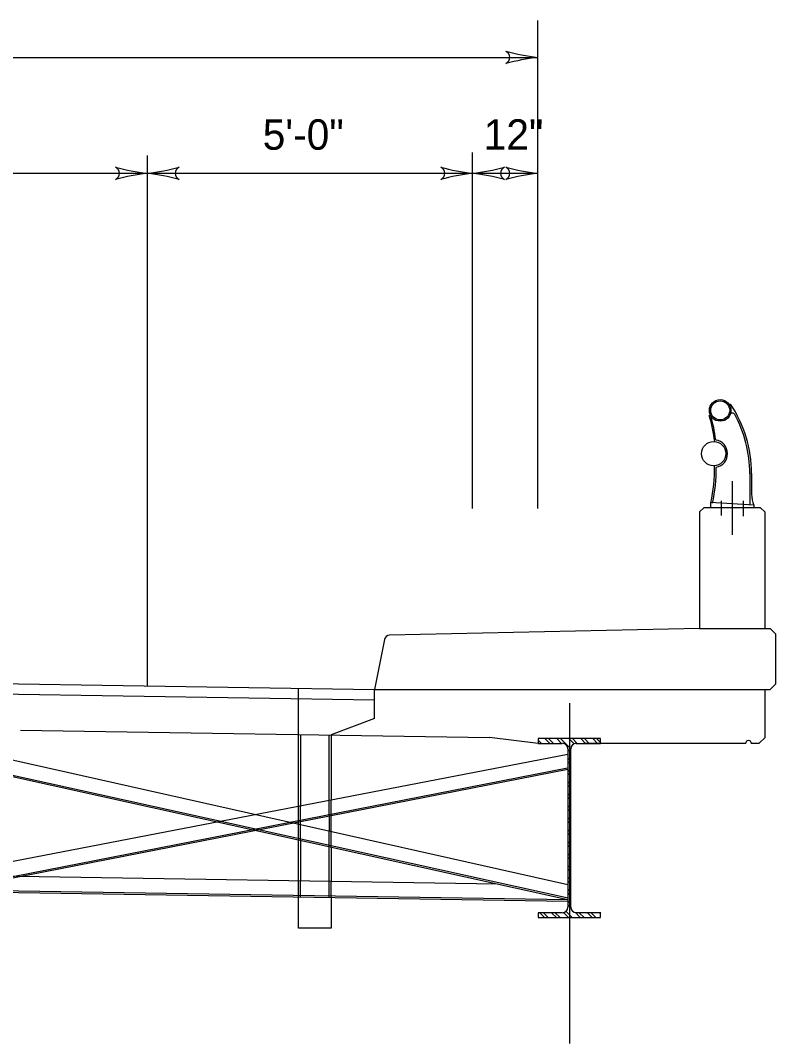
# Model space of a CAD drawing. Extents: x 10803 to 14007, y 6159 to 7440.
# Drawn here: x 13672.33 to 13683.94, y 6286.82 to 6302.55 of the extents above; entities that cross this region are included whole.
import ezdxf

# ---------------------------------------------------------------- set-up
doc = ezdxf.new("R2010")
doc.units = 0
for name, color, linetype in [('BR_X_Rail_Object', 7, 'Continuous'), ('BR_X_Slab_Const_Joint', 7, 'Continuous'), ('BR_X_Slab_Object', 7, 'Continuous'), ('Default', 7, 'Continuous')]:
    doc.layers.add(name, color=color, linetype=linetype)

msp = doc.modelspace()

# ---------------------------------------------------------------- linework, layer by layer
at = {"layer": 'BR_X_Rail_Object'}
for p, q in [((13683.231, 6296.638), (13683.249, 6296.648)), ((13682.922, 6296.472), (13682.941, 6296.478)), ((13683.547, 6295.584), (13683.547, 6295.098)), ((13683.573, 6295.582), (13683.573, 6295.265)), ((13682.943, 6295.133), (13682.943, 6295.051)), ((13683.606, 6295.094), (13682.943, 6295.133)), ((13683.606, 6295.094), (13683.606, 6295.051))]:
    msp.add_line(p, q, dxfattribs=at)
for centre, radius in [((13683.09, 6296.551), 0.166), ((13683.09, 6296.551), 0.146), ((13682.989, 6295.885), 0.187)]:
    msp.add_circle(centre, radius, dxfattribs=at)
for centre, radius, start, end in [((13681.655, 6295.584), 1.916, 359.9287, 33.7121), ((13680.872, 6295.841), 2.146, 6.1531, 17.1122), ((13680.872, 6295.841), 2.165, 6.8219, 17.1122), ((13683.279, 6296.471), 0.0394, 28.6512, 157.265), ((13681.655, 6295.584), 1.89, 359.9287, 28.6512), ((13682.989, 6295.885), 0.213, 280.8945, 81.1945), ((13680.838, 6295.635), 2.165, 346.5742, 1.6594), ((13680.838, 6295.635), 2.192, 346.5742, 1.0208), ((13684.072, 6295.271), 0.499, 180.6213, 200.7537)]:
    msp.add_arc(centre, radius, start, end, dxfattribs=at)
at = {"layer": 'BR_X_Slab_Const_Joint'}
for p, q in [((13682.774, 6293.198), (13683.774, 6293.198)), ((13677.774, 6292.26), (13683.774, 6292.26))]:
    msp.add_line(p, q, dxfattribs=at)
at = {"layer": 'BR_X_Slab_Object'}
for p, q in [((13682.774, 6294.989), (13682.837, 6295.051)), ((13682.774, 6294.989), (13682.774, 6293.198)), ((13683.712, 6295.051), (13682.837, 6295.051)), ((13683.774, 6294.989), (13683.712, 6295.051)), ((13683.774, 6294.989), (13683.774, 6293.198)), ((13682.774, 6293.198), (13678.008, 6293.095)), ((13683.774, 6293.198), (13683.858, 6293.198)), ((13683.858, 6293.198), (13683.941, 6293.114)), ((13683.941, 6293.114), (13683.941, 6292.344)), ((13677.928, 6293.028), (13677.774, 6292.26)), ((13651.774, 6292.666), (13677.774, 6292.26)), ((13651.774, 6292.508), (13677.774, 6292.101)), ((13683.941, 6292.344), (13683.858, 6292.26)), ((13677.774, 6292.101), (13677.774, 6292.26)), ((13683.774, 6292.26), (13683.858, 6292.26)), ((13683.774, 6292.26), (13683.774, 6291.519)), ((13672.334, 6291.637), (13679.542, 6291.524)), ((13680.292, 6291.432), (13679.542, 6291.524)), ((13683.691, 6291.436), (13683.774, 6291.519)), ((13680.993, 6291.436), (13683.483, 6291.436)), ((13683.564, 6291.436), (13683.691, 6291.436))]:
    msp.add_line(p, q, dxfattribs=at)
for centre, radius, start, end in [((13678.01, 6293.012), 0.0833, 91.2327, 168.6901), ((13683.524, 6291.436), 0.0417, 0, 180.0018)]:
    msp.add_arc(centre, radius, start, end, dxfattribs=at)
at = {"layer": 'Default'}
for p, q in [((13680.285, 6295.044), (13680.285, 6302.547)), ((13679.796, 6302.072), (13679.796, 6302.072)), ((13623.264, 6301.979), (13680.285, 6301.979)), ((13679.285, 6295.044), (13679.285, 6300.514)), ((13674.285, 6292.315), (13674.285, 6300.469)), ((13674.285, 6300.196), (13651.774, 6300.196)), ((13679.285, 6300.196), (13674.285, 6300.196)), ((13674.773, 6300.289), (13674.774, 6300.289)), ((13680.285, 6300.196), (13679.285, 6300.196)), ((13679.773, 6300.289), (13679.774, 6300.289)), ((13673.796, 6300.103), (13673.796, 6300.103)), ((13678.796, 6300.103), (13678.796, 6300.103)), ((13679.796, 6300.103), (13679.796, 6300.103)), ((13683.274, 6295.463), (13683.274, 6294.64)), ((13683.107, 6295.16), (13683.107, 6294.933)), ((13683.442, 6295.16), (13683.442, 6294.927)), ((13676.608, 6290.467), (13676.608, 6292.279)), ((13677.774, 6291.814), (13677.774, 6292.101)), ((13680.774, 6292.05), (13680.774, 6286.816)), ((13677.774, 6291.814), (13677.108, 6291.562)), ((13676.639, 6291.57), (13676.639, 6290.473)), ((13677.077, 6290.558), (13677.077, 6291.563)), ((13677.108, 6291.562), (13677.108, 6290.564)), ((13671.128, 6291.42), (13680.747, 6289.261)), ((13681.25, 6291.505), (13680.292, 6291.505)), ((13680.292, 6291.505), (13680.292, 6291.432)), ((13680.342, 6291.432), (13680.292, 6291.482)), ((13680.292, 6291.432), (13680.663, 6291.432)), ((13680.469, 6291.432), (13680.396, 6291.505)), ((13680.526, 6291.432), (13680.453, 6291.505)), ((13680.653, 6291.432), (13680.58, 6291.505)), ((13680.795, 6291.347), (13680.637, 6291.505)), ((13680.846, 6291.423), (13680.764, 6291.505)), ((13680.893, 6291.432), (13680.821, 6291.505)), ((13680.878, 6291.432), (13681.25, 6291.432)), ((13680.878, 6291.432), (13680.878, 6291.432)), ((13681.021, 6291.432), (13680.948, 6291.505)), ((13681.077, 6291.432), (13681.004, 6291.505)), ((13681.205, 6291.432), (13681.132, 6291.505)), ((13681.25, 6291.443), (13681.188, 6291.505)), ((13681.25, 6291.432), (13681.25, 6291.505)), ((13671.128, 6289.411), (13680.747, 6291.265)), ((13680.747, 6291.349), (13680.747, 6288.911)), ((13680.795, 6291.29), (13680.747, 6291.338)), ((13680.795, 6291.163), (13680.747, 6291.211)), ((13680.795, 6288.911), (13680.795, 6291.349)), ((13680.747, 6289.028), (13671.128, 6291.156)), ((13671.128, 6289.174), (13680.743, 6291.057)), ((13680.751, 6289.049), (13671.133, 6291.177)), ((13680.795, 6291.106), (13680.747, 6291.155)), ((13671.128, 6289.153), (13680.747, 6291.037)), ((13680.795, 6290.979), (13680.747, 6291.027)), ((13680.795, 6290.922), (13680.747, 6290.971)), ((13680.795, 6290.795), (13680.747, 6290.843)), ((13680.795, 6290.738), (13680.747, 6290.787)), ((13680.795, 6290.611), (13680.747, 6290.66)), ((13680.795, 6290.555), (13680.747, 6290.603)), ((13676.608, 6289.944), (13676.608, 6290.467)), ((13676.639, 6289.937), (13676.639, 6290.473)), ((13677.077, 6290.318), (13677.077, 6290.558)), ((13677.108, 6290.324), (13677.108, 6290.564)), ((13680.795, 6290.427), (13680.747, 6290.476)), ((13680.795, 6290.371), (13680.747, 6290.419)), ((13677.077, 6290.318), (13677.077, 6290.085)), ((13677.108, 6290.078), (13677.108, 6290.324)), ((13680.795, 6290.244), (13680.747, 6290.292)), ((13680.795, 6290.187), (13680.747, 6290.235)), ((13680.795, 6290.06), (13680.747, 6290.108)), ((13676.608, 6289.316), (13676.608, 6289.944)), ((13677.077, 6289.84), (13677.077, 6290.085)), ((13677.108, 6289.833), (13677.108, 6290.078)), ((13680.795, 6290.003), (13680.747, 6290.051)), ((13676.639, 6289.937), (13676.639, 6289.316)), ((13677.077, 6289.309), (13677.077, 6289.84)), ((13677.108, 6289.833), (13677.108, 6289.309)), ((13680.795, 6289.876), (13680.747, 6289.924)), ((13680.795, 6289.819), (13680.747, 6289.868)), ((13680.795, 6289.692), (13680.747, 6289.74)), ((13680.795, 6289.635), (13680.747, 6289.684)), ((13680.795, 6289.508), (13680.747, 6289.556)), ((13680.795, 6289.452), (13680.747, 6289.5)), ((13679.661, 6289.268), (13671.128, 6289.403)), ((13676.608, 6289.066), (13676.608, 6289.316)), ((13676.639, 6289.066), (13676.639, 6289.316)), ((13680.795, 6289.324), (13680.747, 6289.373)), ((13680.795, 6289.268), (13680.747, 6289.316)), ((13680.747, 6289.027), (13671.128, 6289.179)), ((13680.743, 6289.001), (13671.128, 6289.153)), ((13677.077, 6289.059), (13677.077, 6289.309)), ((13677.108, 6289.059), (13677.108, 6289.309)), ((13680.795, 6289.14), (13680.747, 6289.189)), ((13676.608, 6288.592), (13676.608, 6289.066)), ((13677.108, 6289.059), (13677.108, 6288.592)), ((13680.795, 6289.084), (13680.747, 6289.132)), ((13680.795, 6288.957), (13680.747, 6289.005)), ((13680.813, 6288.755), (13680.718, 6288.85)), ((13680.797, 6288.898), (13680.747, 6288.948)), ((13680.663, 6288.828), (13680.292, 6288.828)), ((13680.292, 6288.828), (13680.292, 6288.755)), ((13680.292, 6288.755), (13681.25, 6288.755)), ((13680.389, 6288.755), (13680.316, 6288.828)), ((13680.445, 6288.755), (13680.372, 6288.828)), ((13680.572, 6288.755), (13680.499, 6288.828)), ((13680.629, 6288.755), (13680.556, 6288.828)), ((13680.756, 6288.755), (13680.68, 6288.831)), ((13680.94, 6288.755), (13680.864, 6288.832)), ((13681.25, 6288.828), (13680.878, 6288.828)), ((13680.997, 6288.755), (13680.924, 6288.828)), ((13681.124, 6288.755), (13681.051, 6288.828)), ((13681.181, 6288.755), (13681.108, 6288.828)), ((13681.25, 6288.813), (13681.235, 6288.828)), ((13681.25, 6288.755), (13681.25, 6288.835)), ((13677.108, 6288.592), (13676.608, 6288.592))]:
    msp.add_line(p, q, dxfattribs=at)
for centre, radius, start, end in [((13680.724, 6305.633), 3.68, 255.3829, 263.1374), ((13680.724, 6298.325), 3.68, 96.8626, 104.6171), ((13674.724, 6303.85), 3.68, 255.3829, 263.1374), ((13674.724, 6296.542), 3.68, 96.8626, 104.6171), ((13673.845, 6303.85), 3.68, 276.8626, 284.6171), ((13673.845, 6296.542), 3.68, 75.3829, 83.1374), ((13679.724, 6303.85), 3.68, 255.3829, 263.1374), ((13679.724, 6296.542), 3.68, 96.8626, 104.6171), ((13678.845, 6303.85), 3.68, 276.8626, 284.6171), ((13678.845, 6296.542), 3.68, 75.3829, 83.1374), ((13680.724, 6303.85), 3.68, 255.3829, 263.1374), ((13680.724, 6296.542), 3.68, 96.8626, 104.6171), ((13680.664, 6291.349), 0.0833, 0, 90), ((13680.878, 6291.349), 0.0833, 90, 180), ((13680.664, 6288.911), 0.0833, 270, 0), ((13680.878, 6288.911), 0.0833, 180, 270)]:
    msp.add_arc(centre, radius, start, end, dxfattribs=at)
for centre, major_axis, start_param, end_param in [((13679.731, 6301.979), (0.125, 0), 5.258637, 7.300638), ((13673.731, 6300.196), (0.125, 0), 5.265733, 7.307734), ((13674.838, 6300.196), (-0.125, 0), 5.265733, 7.307734), ((13678.731, 6300.196), (0.125, 0), 5.265733, 7.307734), ((13679.838, 6300.196), (-0.125, 0), 5.265733, 7.307734), ((13679.731, 6300.196), (0.125, 0), 5.265733, 7.307734)]:
    msp.add_ellipse(centre, major_axis=major_axis, ratio=0.873734, start_param=start_param, end_param=end_param, dxfattribs=at)

# ---------------------------------------------------------------- texts
for s, p in [('5\'-0"', (13676.058, 6300.559)), ('12"', (13679.455, 6300.559))]:
    msp.add_text(s, height=0.468, dxfattribs=at).set_placement(p)

doc.saveas('drawing.dxf')
